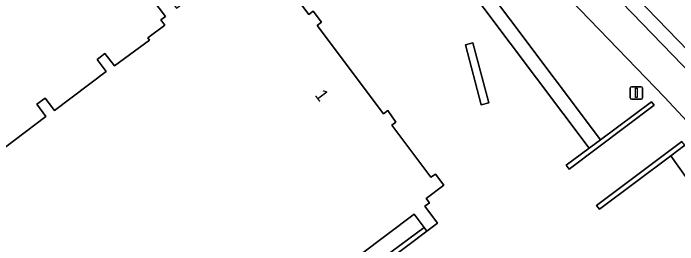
# Model space of a CAD drawing. Extents: x 161087 to 161926, y 382572 to 383873.
# Drawn here: x 161400.3 to 161454.1, y 383099.2 to 383118 of the extents above; entities that cross this region are included whole.
import ezdxf

# ---------------------------------------------------------------- set-up
doc = ezdxf.new("R2010")
doc.units = 0
for name, color, linetype in [('IMGEO_Erf', 7, 'Continuous'), ('IMGEO_Lichtmast', 7, 'Continuous'), ('IMGEO_Lijnafwatering', 7, 'Continuous'), ('IMGEO_Muur', 7, 'Continuous'), ('IMGEO_Pand', 7, 'Continuous'), ('IMGEO_Pand_nummerreeks', 7, 'Continuous'), ('IMGEO_Voetgangersgebied_gesloten', 7, 'Continuous'), ('IMGEO_Voetgangersgebied_open', 7, 'Continuous'), ('IMGEO_Voetpad_op_trap', 7, 'Continuous')]:
    doc.layers.add(name, color=color, linetype=linetype)

msp = doc.modelspace()

# ---------------------------------------------------------------- linework, layer by layer
at = {"layer": 'IMGEO_Erf'}
for points in [[(161407.788, 383113.248), (161407.066, 383114.206), (161407.694, 383114.705), (161408.465, 383113.687), (161411.291, 383115.779), (161411.154, 383115.964), (161412.537, 383116.987), (161412.216, 383117.421), (161412.586, 383117.695), (161411.568, 383119.069), (161412.449, 383119.72), (161413.473, 383118.365), (161417.788, 383121.59), (161416.76, 383122.965), (161417.053, 383123.186), (161416.541, 383123.832), (161416.243, 383123.675), (161416.444, 383123.446)], [(161398.651, 383106.365), (161402.916, 383109.578), (161402.164, 383110.576), (161402.843, 383111.088), (161403.595, 383110.089), (161407.788, 383113.248)]]:
    msp.add_lwpolyline(points, dxfattribs=at)
at = {"layer": 'IMGEO_Lichtmast'}
for p, q in [((161450.223, 383111.103), (161450.223, 383111.903)), ((161450.223, 383111.903), (161450.223, 383111.103)), ((161450.323, 383112.003), (161451.113, 383112.003)), ((161451.113, 383112.003), (161450.323, 383112.003)), ((161451.213, 383111.903), (161451.213, 383111.103)), ((161451.213, 383111.103), (161451.213, 383111.903)), ((161451.113, 383111.003), (161450.323, 383111.003)), ((161450.323, 383111.003), (161451.113, 383111.003))]:
    msp.add_line(p, q, dxfattribs=at)
msp.add_lwpolyline([(161450.643, 383111.878), (161450.793, 383111.878), (161450.793, 383111.128), (161450.643, 383111.128), (161450.643, 383111.878)], dxfattribs=at)
for centre, start, end in [((161450.323, 383111.903), 90, 180), ((161450.323, 383111.903), 90, 180), ((161451.113, 383111.903), 0, 90), ((161451.113, 383111.903), 360, 90), ((161450.323, 383111.103), 180, 270), ((161450.323, 383111.103), 180, 270), ((161451.113, 383111.103), 270, 0), ((161451.113, 383111.103), 270, 0)]:
    msp.add_arc(centre, 0.1, start, end, dxfattribs=at)
at = {"layer": 'IMGEO_Lijnafwatering'}
msp.add_lwpolyline([(161466.769, 383101.02), (161449.541, 383118.836)], dxfattribs=at)
at = {"layer": 'IMGEO_Muur'}
for points in [[(161445.045, 383105.643), (161445.28, 383105.337), (161452.173, 383110.498), (161451.944, 383110.791), (161447.816, 383107.71), (161446.884, 383107.015)], [(161454.411, 383107.561), (161447.499, 383102.386), (161447.724, 383102.071), (161453.51, 383106.413), (161454.645, 383107.265)], [(161433.751, 383100.298), (161433.532, 383100.592), (161430.336, 383098.221), (161430.574, 383097.899)]]:
    msp.add_lwpolyline(points, close=True, dxfattribs=at)
at = {"layer": 'IMGEO_Pand'}
for points in [[(161428.365, 383098.378), (161432.731, 383101.667), (161433.532, 383100.592), (161433.751, 383100.298), (161434.622, 383100.943), (161433.597, 383102.324), (161433.958, 383102.592), (161433.69, 383102.953), (161435.135, 383104.026), (161434.464, 383104.929), (161434.087, 383104.664), (161430.91, 383108.89), (161431.245, 383109.141), (161430.606, 383110.07), (161430.238, 383109.806), (161424.866, 383116.965), (161425.227, 383117.235), (161424.562, 383118.12), (161424.194, 383117.846), (161421.021, 383122.103)], [(161411.568, 383119.069), (161412.586, 383117.695), (161412.216, 383117.421), (161412.537, 383116.987), (161411.154, 383115.964), (161411.291, 383115.779), (161408.465, 383113.687), (161407.694, 383114.705), (161407.066, 383114.206), (161407.788, 383113.248), (161403.595, 383110.089), (161402.843, 383111.088), (161402.164, 383110.576), (161402.916, 383109.578), (161398.651, 383106.365)]]:
    msp.add_lwpolyline(points, dxfattribs=at)
at = {"layer": 'IMGEO_Voetgangersgebied_gesloten'}
msp.add_lwpolyline([(161427.23, 383145.42), (161424.134, 383142.986), (161425.775, 383141.093), (161425.992, 383140.842), (161442.393, 383122.164), (161452.996, 383111.144), (161455.559, 383108.39), (161465.248, 383098.487), (161465.694, 383097.915), (161468.435, 383100.938), (161445.647, 383124.486)], close=True, dxfattribs=at)
at = {"layer": 'IMGEO_Voetgangersgebied_open'}
for points in [[(161431.78, 383147.287), (161430.231, 383146.746), (161427.23, 383145.42), (161445.647, 383124.486), (161468.435, 383100.938), (161471.604, 383103.257), (161449.116, 383126.46)], [(161421.021, 383122.103), (161424.194, 383117.846), (161424.562, 383118.12), (161425.227, 383117.235), (161424.866, 383116.965), (161430.238, 383109.806), (161430.606, 383110.07), (161431.245, 383109.141), (161430.91, 383108.89), (161434.087, 383104.664), (161434.464, 383104.929), (161435.135, 383104.026), (161433.69, 383102.953), (161433.958, 383102.592), (161433.597, 383102.324), (161434.622, 383100.943), (161433.751, 383100.298), (161430.574, 383097.899)], [(161455.559, 383108.39), (161452.996, 383111.144), (161442.393, 383122.164)], [(161460.242, 383096.929), (161453.51, 383106.413), (161447.724, 383102.071), (161447.499, 383102.386), (161454.411, 383107.561)], [(161430.336, 383098.221), (161433.532, 383100.592), (161432.731, 383101.667), (161428.365, 383098.378)]]:
    msp.add_lwpolyline(points, dxfattribs=at)
for points in [[(161425.483, 383135.522), (161421.741, 383132.603), (161424.103, 383129.443), (161423.777, 383129.207), (161420.731, 383133.357), (161421.028, 383133.582), (161425.705, 383137.161), (161447.816, 383107.71), (161451.944, 383110.791), (161452.173, 383110.498), (161445.28, 383105.337), (161445.045, 383105.643), (161446.884, 383107.015)], [(161438.761, 383110.684), (161437.471, 383115.543), (161436.871, 383115.384), (161438.161, 383110.525)], [(161436.871, 383115.384), (161437.471, 383115.543), (161438.761, 383110.684), (161438.161, 383110.525)]]:
    msp.add_lwpolyline(points, close=True, dxfattribs=at)
at = {"layer": 'IMGEO_Voetpad_op_trap'}
for points in [[(161447.816, 383107.71), (161425.705, 383137.161), (161421.028, 383133.582), (161421.741, 383132.603), (161425.483, 383135.522), (161446.884, 383107.015)], [(161453.51, 383106.413), (161460.242, 383096.929), (161439.406, 383081.335), (161432.854, 383090.061), (161431.423, 383088.954), (161439.049, 383078.884), (161462.705, 383096.578), (161454.645, 383107.265)]]:
    msp.add_lwpolyline(points, close=True, dxfattribs=at)

# ---------------------------------------------------------------- texts
at = {"layer": 'IMGEO_Pand_nummerreeks'}
msp.add_text('1', height=1, rotation=306.4857, dxfattribs=at).set_placement((161424.644, 383111.316))

doc.saveas('drawing.dxf')
